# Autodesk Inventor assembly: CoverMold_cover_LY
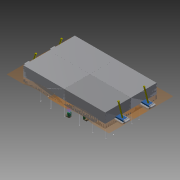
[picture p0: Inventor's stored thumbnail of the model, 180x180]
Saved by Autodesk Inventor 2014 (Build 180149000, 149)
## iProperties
Created: 2009-12
Part Number: CoverMold_cover_LY
Document SubType Name: Assembly
Designer: gaom
Author: gaom
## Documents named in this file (10)
- C:\Users\iTools\Desktop\tutorial files\Mold\CoverMold\Cover Mold\CoverMold_cover_LY.iam
- C:\Users\iTools\Desktop\tutorial files\Mold\CoverMold\Cover Mold\CoverMold_cover_PZ.iam
- C:\Users\iTools\Desktop\tutorial files\Mold\CoverMold\Cover Mold\CoverMold_cover_CV_2.ipt
- C:\Users\iTools\Desktop\tutorial files\Mold\CoverMold\Cover Mold\CoverMold_cover_CV_3.ipt
- C:\Users\iTools\Desktop\tutorial files\Mold\CoverMold\Cover Mold\CoverMold_cover_CV_4.ipt
- C:\Users\iTools\Desktop\tutorial files\Mold\CoverMold\Cover Mold\CoverMold_cover_CV_1.ipt
- C:\Users\iTools\Desktop\tutorial files\Mold\CoverMold\Cover Mold\CoverMold_cover_CR_2.ipt
- C:\Users\iTools\Desktop\tutorial files\Mold\CoverMold\Cover Mold\CoverMold_cover_CR_3.ipt
- C:\Users\iTools\Desktop\tutorial files\Mold\CoverMold\Cover Mold\CoverMold_cover_CR_4.ipt
- C:\Users\iTools\Desktop\tutorial files\Mold\CoverMold\Cover Mold\CoverMold_cover_CR_1.ipt
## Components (12 placed, 9 different names)
1. CoverMold_cover_PZ:1 [sub-assembly] — Flush:1, Flush:2, Flush:3, Flush:13, Flush:14, Flush:15, Flush:25, Flush:26, Flush:27, Flush:37, Flush:38, Flush:39
2. CoverMold_cover_PZ:2 [sub-assembly] — Flush:4, Flush:5, Flush:6, Flush:16, Flush:17, Flush:18, Flush:28, Flush:29, Flush:30, Flush:40, Flush:41, Flush:42
3. CoverMold_cover_PZ:3 [sub-assembly] — Flush:7, Flush:8, Flush:9, Flush:19, Flush:20, Flush:21, Flush:31, Flush:32, Flush:33, Flush:43, Flush:44, Flush:45
4. CoverMold_cover_PZ:4 [sub-assembly] — Flush:10, Flush:11, Flush:12, Flush:22, Flush:23, Flush:24, Flush:34, Flush:35, Flush:36, Flush:46, Flush:47, Flush:48
5. CoverMold_cover_CV_1:1 — Flush:13, Flush:14, Flush:15, Flush:37, Flush:38, Flush:39
6. CoverMold_cover_CV_2:1 — Flush:16, Flush:17, Flush:18, Flush:40, Flush:41, Flush:42
7. CoverMold_cover_CV_3:1 — Flush:19, Flush:20, Flush:21, Flush:43, Flush:44, Flush:45
8. CoverMold_cover_CV_4:1 — Flush:22, Flush:23, Flush:24, Flush:46, Flush:47, Flush:48
9. CoverMold_cover_CR_1:1 — Flush:25, Flush:26, Flush:27
10. CoverMold_cover_CR_2:1 — Flush:28, Flush:29, Flush:30
11. CoverMold_cover_CR_3:1 — Flush:31, Flush:32, Flush:33
12. CoverMold_cover_CR_4:1 — Flush:34, Flush:35, Flush:36
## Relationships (48: Flush 48)
- Flush:1: CoverMold_cover_PZ:1
- Flush:2: CoverMold_cover_PZ:1
- Flush:3: CoverMold_cover_PZ:1
- Flush:4: CoverMold_cover_PZ:2
- Flush:5: CoverMold_cover_PZ:2
- Flush:6: CoverMold_cover_PZ:2
- Flush:7: CoverMold_cover_PZ:3
- Flush:8: CoverMold_cover_PZ:3
- Flush:9: CoverMold_cover_PZ:3
- Flush:10: CoverMold_cover_PZ:4
- Flush:11: CoverMold_cover_PZ:4
- Flush:12: CoverMold_cover_PZ:4
- Flush:13: CoverMold_cover_PZ:1 ↔ CoverMold_cover_CV_1:1
- Flush:14: CoverMold_cover_PZ:1 ↔ CoverMold_cover_CV_1:1
- Flush:15: CoverMold_cover_PZ:1 ↔ CoverMold_cover_CV_1:1
- Flush:16: CoverMold_cover_PZ:2 ↔ CoverMold_cover_CV_2:1
- Flush:17: CoverMold_cover_PZ:2 ↔ CoverMold_cover_CV_2:1
- Flush:18: CoverMold_cover_PZ:2 ↔ CoverMold_cover_CV_2:1
- Flush:19: CoverMold_cover_PZ:3 ↔ CoverMold_cover_CV_3:1
- Flush:20: CoverMold_cover_PZ:3 ↔ CoverMold_cover_CV_3:1
- Flush:21: CoverMold_cover_PZ:3 ↔ CoverMold_cover_CV_3:1
- Flush:22: CoverMold_cover_PZ:4 ↔ CoverMold_cover_CV_4:1
- Flush:23: CoverMold_cover_PZ:4 ↔ CoverMold_cover_CV_4:1
- Flush:24: CoverMold_cover_PZ:4 ↔ CoverMold_cover_CV_4:1
- Flush:25: CoverMold_cover_PZ:1 ↔ CoverMold_cover_CR_1:1
- Flush:26: CoverMold_cover_PZ:1 ↔ CoverMold_cover_CR_1:1
- Flush:27: CoverMold_cover_PZ:1 ↔ CoverMold_cover_CR_1:1
- Flush:28: CoverMold_cover_PZ:2 ↔ CoverMold_cover_CR_2:1
- Flush:29: CoverMold_cover_PZ:2 ↔ CoverMold_cover_CR_2:1
- Flush:30: CoverMold_cover_PZ:2 ↔ CoverMold_cover_CR_2:1
- Flush:31: CoverMold_cover_PZ:3 ↔ CoverMold_cover_CR_3:1
- Flush:32: CoverMold_cover_PZ:3 ↔ CoverMold_cover_CR_3:1
- Flush:33: CoverMold_cover_PZ:3 ↔ CoverMold_cover_CR_3:1
- Flush:34: CoverMold_cover_PZ:4 ↔ CoverMold_cover_CR_4:1
- Flush:35: CoverMold_cover_PZ:4 ↔ CoverMold_cover_CR_4:1
- Flush:36: CoverMold_cover_PZ:4 ↔ CoverMold_cover_CR_4:1
- Flush:37: CoverMold_cover_PZ:1 ↔ CoverMold_cover_CV_1:1
- Flush:38: CoverMold_cover_PZ:1 ↔ CoverMold_cover_CV_1:1
- Flush:39: CoverMold_cover_PZ:1 ↔ CoverMold_cover_CV_1:1
- Flush:40: CoverMold_cover_PZ:2 ↔ CoverMold_cover_CV_2:1
- Flush:41: CoverMold_cover_PZ:2 ↔ CoverMold_cover_CV_2:1
- Flush:42: CoverMold_cover_PZ:2 ↔ CoverMold_cover_CV_2:1
- Flush:43: CoverMold_cover_PZ:3 ↔ CoverMold_cover_CV_3:1
- Flush:44: CoverMold_cover_PZ:3 ↔ CoverMold_cover_CV_3:1
- Flush:45: CoverMold_cover_PZ:3 ↔ CoverMold_cover_CV_3:1
- Flush:46: CoverMold_cover_PZ:4 ↔ CoverMold_cover_CV_4:1
- Flush:47: CoverMold_cover_PZ:4 ↔ CoverMold_cover_CV_4:1
- Flush:48: CoverMold_cover_PZ:4 ↔ CoverMold_cover_CV_4:1
